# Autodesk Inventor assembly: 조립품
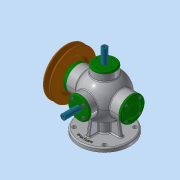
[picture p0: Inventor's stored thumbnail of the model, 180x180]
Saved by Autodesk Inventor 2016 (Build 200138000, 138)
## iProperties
Created: 2019-11
Part Number: 조립품
Material: 일반
Document SubType Name: Assembly
Designer: user
Mass: 3778.22 g
Surface Area: 2410.88 cm^2
Volume: 904.614 cm^3
Density: 4.17661 g/cm^3
Author: user
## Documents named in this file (17)
- C:\Users\user\Desktop\391120V1001\조립품.iam
- C:\Users\user\Desktop\391120V1001\V-벨트풀리.ipt
- C:\Users\user\Desktop\391120V1001\너트 M8x1.ipt
- C:\Users\user\Desktop\391120V1001\뒤커버.ipt
- C:\Users\user\Desktop\391120V1001\베어링 6202.ipt
- C:\Users\user\Desktop\391120V1001\본체.ipt
- C:\Users\user\Desktop\391120V1001\본체커버.ipt
- C:\Users\user\Desktop\391120V1001\볼트 M4.ipt
- C:\Users\user\Desktop\391120V1001\스프링1.ipt
- C:\Users\user\Desktop\391120V1001\스프링2.ipt
- C:\Users\user\Desktop\391120V1001\슬라이드 커버.ipt
- C:\Users\user\Desktop\391120V1001\슬라이드.ipt
- C:\Users\user\Desktop\391120V1001\앞커버.ipt
- C:\Users\user\Desktop\391120V1001\오일 실.ipt
- C:\Users\user\Desktop\391120V1001\와셔 8x17.ipt
- C:\Users\user\Desktop\391120V1001\축.ipt
- C:\Users\user\Desktop\391120V1001\키 4x4.ipt
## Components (1 placed, 1 different names)
1. V-벨트풀리:1
